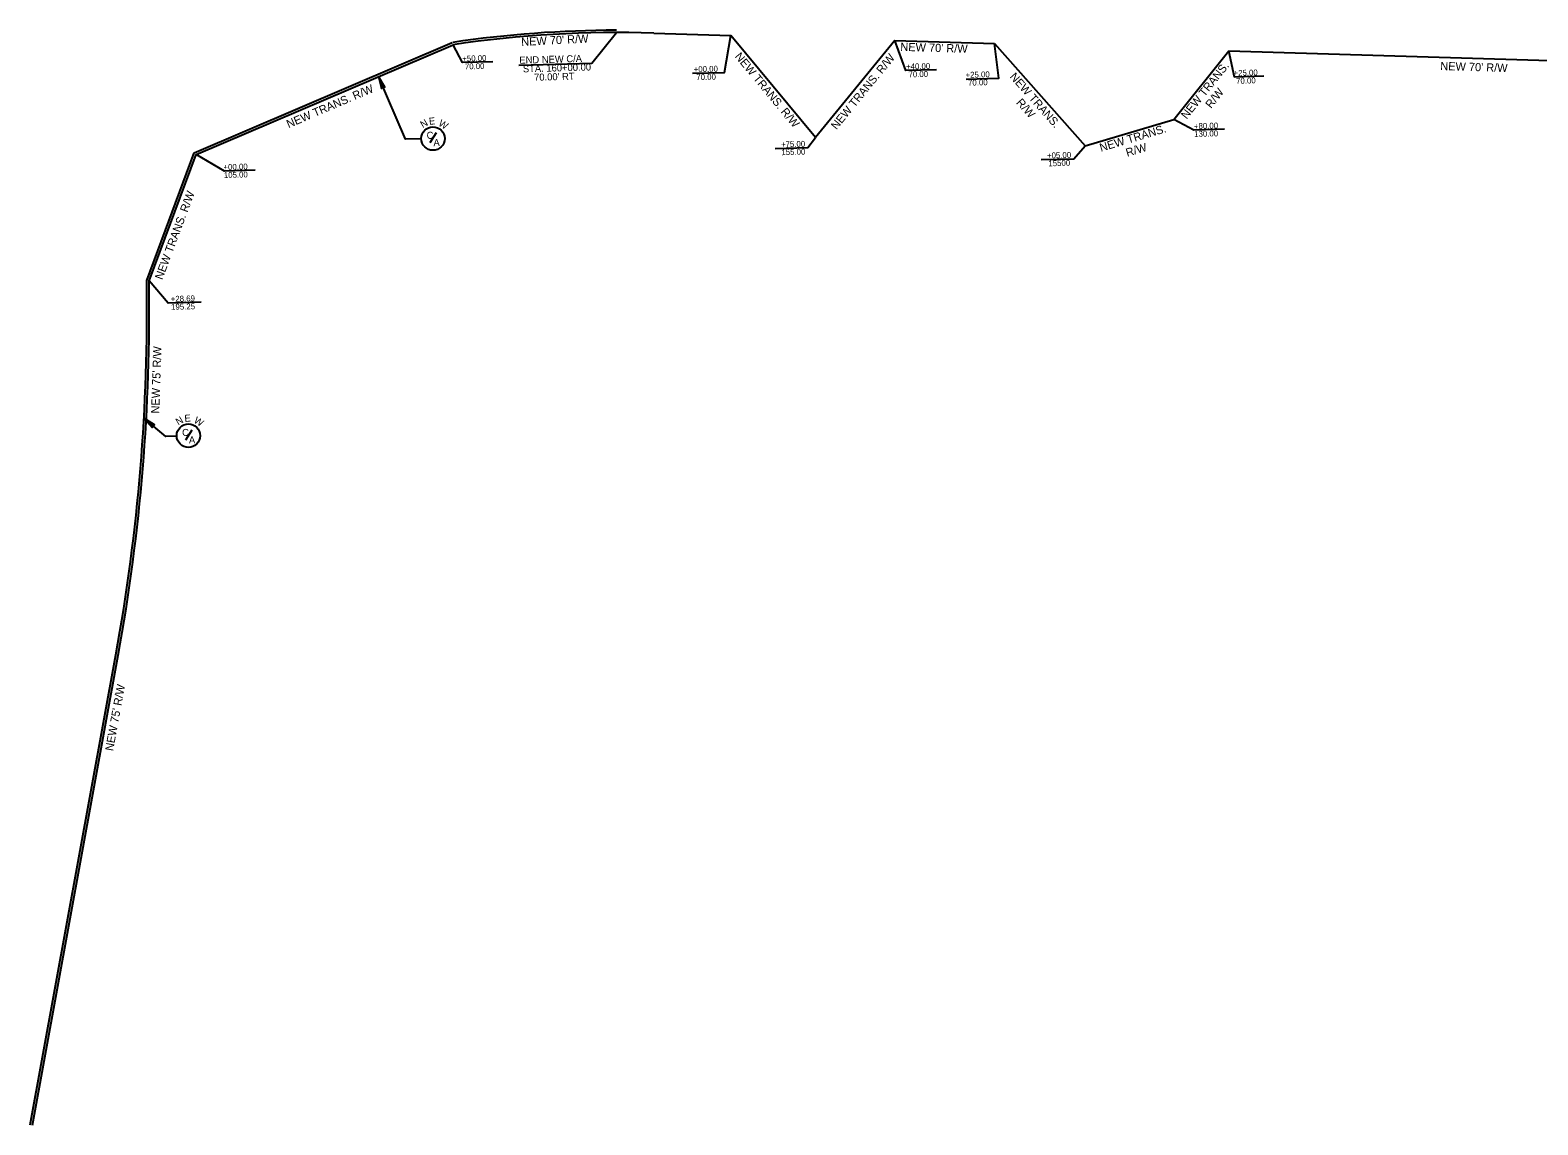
# Model space of a CAD drawing. Extents: x 2003184 to 2010449, y 855784 to 861212.
# Drawn here: x 2005557 to 2006844, y 857163 to 858097 of the extents above; entities that cross this region are included whole.
import ezdxf

# ---------------------------------------------------------------- set-up
doc = ezdxf.new("R2010")
doc.units = 0
for name, color, linetype in [('RD_PD_Control_Access', 7, 'Continuous'), ('RD_PD_RW', 7, 'Continuous'), ('RD_PD_RW_TX', 7, 'Continuous')]:
    doc.layers.add(name, color=color, linetype=linetype)

msp = doc.modelspace()

# ---------------------------------------------------------------- linework, layer by layer
at = {"layer": 'RD_PD_Control_Access'}
for p, q in [((2005697.2, 857992.8), (2005917.5, 858086.9)), ((2005903.8, 858009.7), (2005898.4, 858001.2)), ((2005656.7, 857883.9), (2005697.2, 857992.8)), ((2005695.1, 857756.1), (2005689.7, 857747.5)), ((2005557.2, 857163.1), (2005630.4, 857564.3))]:
    msp.add_line(p, q, dxfattribs=at)
for points in [[(2005974.4, 858067.5), (2006036.7, 858069.2), (2006057.6, 858095.4)], [(2005891, 858004.7), (2005877.6, 858004.3), (2005854.5, 858057.8)], [(2005682.3, 857751), (2005673.1, 857750.7), (2005654.3, 857766.2)]]:
    msp.add_lwpolyline(points, dxfattribs=at)
for points in [[(2005854.5, 858057.8), (2005857.2, 858047.7), (2005858, 858049.7), (2005860, 858048.9)], [(2005654.3, 857766.2), (2005661.4, 857758.4), (2005661.1, 857760.6), (2005663.3, 857760.7)]]:
    msp.add_lwpolyline(points, close=True, dxfattribs=at)
for centre in [(2005901, 858004.9), (2005692.3, 857751.3)]:
    msp.add_circle(centre, 10, dxfattribs=at)
for centre, radius, start, end in [((2006059.8, 857126.4), 971, 90.1294, 98.4012), ((2004023.9, 857857.2), 1633, 349.6659, 0.9351)]:
    msp.add_arc(centre, radius, start, end, dxfattribs=at)
at = {"layer": 'RD_PD_RW'}
for p, q in [((2005698.8, 857991.3), (2005918.2, 858085)), ((2006089.5, 858095), (2006155.3, 858093)), ((2006227.6, 858005.7), (2006155.3, 858093)), ((2006295.2, 858088.7), (2006227.6, 858005.7)), ((2006295.2, 858088.7), (2006380.2, 858086.1)), ((2006380.2, 858086.1), (2006457.5, 857998.7)), ((2006533.3, 858021.3), (2006580.1, 858079.9)), ((2006580.1, 858079.9), (2006904.9, 858070)), ((2006457.5, 857998.7), (2006533.3, 858021.3)), ((2005658.7, 857883.5), (2005698.8, 857991.3)), ((2005559.2, 857162.7), (2005632.4, 857563.9))]:
    msp.add_line(p, q, dxfattribs=at)
for centre, radius, start, end in [((2006059.8, 857126.4), 969, 88.2422, 98.4012), ((2004023.9, 857857.2), 1635, 349.6659, 0.9219)]:
    msp.add_arc(centre, radius, start, end, dxfattribs=at)
at = {"layer": 'RD_PD_RW_TX'}
for points in [[(2005952, 858070.4), (2005926.2, 858069.7), (2005918.2, 858085)], [(2006122.5, 858060.6), (2006149.7, 858061.4), (2006155.3, 858093)], [(2006330.7, 858063.6), (2006304.7, 858062.9), (2006295.2, 858088.7)], [(2006356.1, 858055.7), (2006384, 858056.5), (2006380.2, 858086.1)], [(2006610.1, 858058.1), (2006585, 858057.4), (2006580.1, 858079.9)], [(2006576.4, 858012.9), (2006550.4, 858012.2), (2006533.3, 858021.3)], [(2006193.1, 857996.4), (2006220.8, 857997.2), (2006227.6, 858005.7)], [(2006420.1, 857986.9), (2006447.8, 857987.7), (2006457.5, 857998.7)], [(2005749.2, 857977.8), (2005723.1, 857977.1), (2005698.8, 857991.3)], [(2005703.1, 857865.3), (2005675, 857864.5), (2005658.7, 857883.5)]]:
    msp.add_lwpolyline(points, dxfattribs=at)

# ---------------------------------------------------------------- texts
at = {"layer": 'RD_PD_Control_Access'}
for s, rotation, p in [('END NEW C/A', 1.6093, (2005974.8, 858068.8)), ('STA. 160+00.00', 1.6093, (2005977.8, 858061.4)), ("70.00' RT", 1.6093, (2005987.4, 858054.2)), ('N', 30.9213, (2005892.4, 858013.7)), ('E', 5.803, (2005897.9, 858016.6)), ('W', 328.1255, (2005905.1, 858016.4)), ('C', 1.6093, (2005895.7, 858004.6)), ('A', 1.6093, (2005901.5, 857998.4)), ('N', 30.9213, (2005683.6, 857760)), ('E', 5.803, (2005689.2, 857763)), ('W', 328.1255, (2005696.4, 857762.8)), ('C', 1.6093, (2005687, 857751)), ('A', 1.6093, (2005692.8, 857744.7))]:
    msp.add_text(s, height=6, rotation=rotation, dxfattribs=at).set_placement(p)
at = {"layer": 'RD_PD_RW_TX'}
for s, height, rotation, p in [("NEW 70' R/W", 7, 3.0322, (2005976.5, 858083.9)), ("NEW 70' R/W", 7, 358.2422, (2006299.8, 858079.8)), ('+50.00', 5, 1.6093, (2005926.1, 858070.6)), ('NEW TRANS. R/W', 7, 309.6658, (2006158.2, 858074.8)), ('NEW TRANS. R/W', 7, 50.8368, (2006245.4, 858012)), ("NEW 70' R/W", 7, 358.2422, (2006760.6, 858063.4)), ('70.00', 5, 1.6093, (2005928.3, 858063.9)), ('+00.00', 5, 1.6093, (2006123.6, 858061.5)), ('70.00', 5, 1.6093, (2006125.8, 858054.8)), ('+40.00', 5, 1.6093, (2006304.8, 858063.8)), ('70.00', 5, 1.6093, (2006306.9, 858057.1)), ('+25.00', 5, 1.6093, (2006355.6, 858056.7)), ('NEW TRANS.', 7, 311.5065, (2006392.8, 858057.4)), ('NEW TRANS.', 7, 51.3723, (2006544.2, 858021)), ('+25.00', 5, 1.6093, (2006584.3, 858058.3)), ('70.00', 5, 1.6093, (2006586.5, 858051.6)), ('NEW TRANS. R/W', 7, 23.1236, (2005777.8, 858013.7)), ('70.00', 5, 1.6093, (2006357.7, 858050)), ('R/W', 7, 51.3723, (2006565, 858030.2)), ('R/W', 7, 311.5065, (2006398.3, 858035.3)), ('+80.00', 5, 1.6093, (2006550.5, 858013)), ('NEW TRANS.', 7, 16.6771, (2006471.1, 857993.6)), ('130.00', 5, 1.6093, (2006550.7, 858006.3)), ('+75.00', 5, 1.6093, (2006198.1, 857997.4)), ('155.00', 5, 1.6093, (2006198.4, 857990.7)), ('+05.00', 5, 1.6093, (2006425.1, 857987.9)), ('R/W', 7, 16.6771, (2006493.5, 857989.3)), ('+00.00', 5, 1.6093, (2005722.3, 857978)), ('15500', 5, 1.6093, (2006426.3, 857981.2)), ('105.00', 5, 1.6093, (2005722.6, 857971.2)), ('NEW TRANS. R/W', 7, 69.5931, (2005670, 857883.9)), ('+28.69', 5, 1.6093, (2005677.3, 857865.5)), ('195.25', 5, 1.6093, (2005677.6, 857858.7)), ("NEW 75' R/W", 7, 88.0614, (2005667.4, 857770.1)), ("NEW 75' R/W", 7, 79.6659, (2005628, 857481.8))]:
    msp.add_text(s, height=height, rotation=rotation, dxfattribs=at).set_placement(p)

doc.saveas('drawing.dxf')
